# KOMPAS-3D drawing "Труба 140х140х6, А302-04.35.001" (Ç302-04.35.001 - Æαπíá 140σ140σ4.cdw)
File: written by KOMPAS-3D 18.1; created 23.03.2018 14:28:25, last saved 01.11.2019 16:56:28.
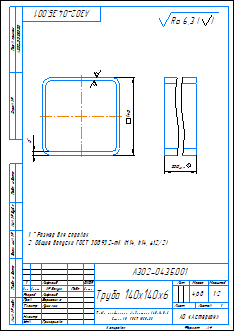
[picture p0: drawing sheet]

Sheet 1: A4, portrait

Document properties: Автор: Милов; Масса: 4.6797; Параметр неуказанной шероховатости: Ra 6,3; Полное имя файла: ..\3Д\А302-00.35.001 - Труба 140х140х4.m3d

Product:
- Part/product: Труба 140х140х6  | designation А302-04.35.001
    Масса: 4.6797
    Раздел спецификации: Детали
    Форматы листов документа: A4
- Part/product: Труба 140х140х4  | designation А302-00.35.001
    Масса: 4.39548
    Раздел спецификации: Детали
    Форматы листов документа: A4
  - Component: Труба 140х140х4  | designation А302-00.35.001  | Масса: 4.4; Раздел спецификации: Детали; Форматы листов документа: A4
- Part/product: Труба 140х140х6  | designation А302-05.35.001
    Масса: 2.81713
    Раздел спецификации: Детали
    Форматы листов документа: A4

Title block, sheet 1: Наименование: Труба 140х140х6; designation: А302-04.35.001; Масса: 4,68; scale: 1:2; Количество листов документа: 1; organisation: АО «Астерион»; Форматы листов документа: A4; stored path: \\192.168.87.28\Konstructor_doc\Мембранные насосы\Мембранный электропривод\А302-00.00.000 - ASTRA-302 (МЭ200)\Чертежи\А302-00.35.001 - Труба 140х140х4.cdw; Разработал: Лифлянд; Проверил: Борисенко; Т. контр.: Лучихин; Утвердил: Григорьева

Views: Вид 1, Спереди, Проекционный вид 2
Referenced files in Z:\Мембранные насосы\Мембранный электропривод\А302-00.00.000 - ASTRA-302 (МЭ200)\3Д\: А302-00.35.001 - Труба 140х140х4.m3d
Referenced files in D:\Мембранные насосы\Мембранный электропривод\А302-00.00.000 - ASTRA-302 (МЭ200)\3Д\: А302-00.35.001 - Труба 140х140х4.m3d
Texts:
  Труба профильная квадратная 140х140х6
  Ra 6,3
  Ra 6,3 ( )
Dimensions and other numbers on the sheet: 140; 6; 200; 1; 1:2; 4,68; 01.11.2019

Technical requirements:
  *Размер для справок.
  Общие допуски ГОСТ 30893.2-mK (H14, h14,  t2/2).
